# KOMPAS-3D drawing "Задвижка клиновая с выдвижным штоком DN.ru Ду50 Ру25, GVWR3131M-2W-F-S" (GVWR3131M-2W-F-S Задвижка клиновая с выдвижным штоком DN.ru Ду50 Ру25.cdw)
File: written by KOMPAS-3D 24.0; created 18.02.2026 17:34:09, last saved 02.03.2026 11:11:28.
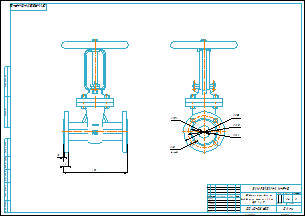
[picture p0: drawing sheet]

Document properties: art: D040-07875; Автор: R2D2; Форматы листов документа: A2; Полное имя файла: GVWR3131M-2W-F-S Задвижка клиновая с выдвижным штоком DN.ru Ду50 Ру25.m3d; Масса: 14; Наименование: Задвижка клиновая с выдвижным штоком DN.ru Ду50 Ру25; Количество листов документа: 1; Примечание: D040-08600

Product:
- Part/product: Задвижка клиновая с выдвижным штоком DN.ru Ду50 Ру25  | designation GVWR3131M-2W-F-S
    Масса: 14
    Раздел спецификации: Прочие изделия
    Примечание: D040-08600

Views: Вид 1, Спереди, Проекционный вид 2
Referenced files in E:\Работа\Зайцев\GVWR3131M-2W-F-S Задвижка клиновая с выдвижным штоком DN.ru Ду50-200 Ру63\DN50\: GVWR3131M-2W-F-S Задвижка клиновая с выдвижным штоком DN.ru Ду50 Ру63.m3d
Referenced files in E:\Работа\Зайцев\GVWR3131M-2W-F-S Задвижка клиновая 30нж64нж DN.ru  Ду50-150 Ру25\исходные данные\DN50\dn50\: GVWR3131M-2W-F-S Задвижка клиновая с выдвижным штоком DN.ru Ду50 Ру25.m3d
Referenced files in E:\Работа\Зайцев\Для компаса\: чертеж DN.ru.cdt
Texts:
  GVWR3131M-2W-F-S
  Диаметральный размер
  чертеж DN.ru.cdt
  Задвижка клиновая с
  выдвижным штоком DN.ru
  Ду50 Ру25
  Задвижка клиновая с выдвижным штоком DN.ru Ду50 Ру25
  GVWR3131M-2W-F-S Задвижка клиновая с выдвижным штоком DN.ru Ду50 Ру25
Dimensions and other numbers on the sheet: 0; 3; 2; 4; 250; 20; 125; 50; 18; 4 отв.; 160; 100; 1:2; 1; 14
